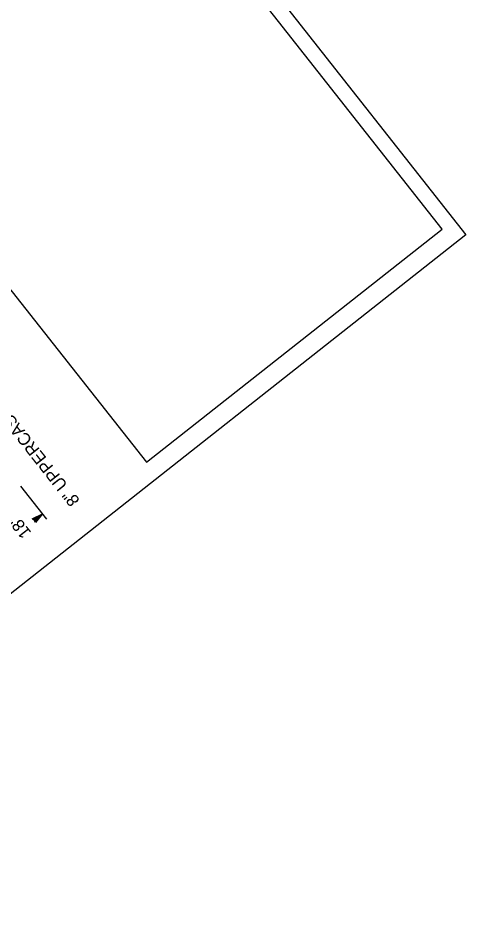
# Model space of a CAD drawing. Extents: x 672438 to 673980, y 1673259 to 1674850.
# Drawn here: x 673827.5 to 673979.7, y 1673259 to 1673565 of the extents above; entities that cross this region are included whole.
import ezdxf

# ---------------------------------------------------------------- set-up
doc = ezdxf.new("R2010")
doc.units = 0
doc.layers.add('61', color=7, linetype='Continuous')
doc.layers.add('Level 1', color=7, linetype='Continuous')

msp = doc.modelspace()

# ---------------------------------------------------------------- linework, layer by layer
at = {"layer": '61'}
msp.add_lwpolyline([(673971.58, 1673493.35), (673840.54, 1673659.58), (673740.04, 1673580.35), (673871.09, 1673414.13)], close=True, dxfattribs=at)
at = {"layer": 'Level 1'}
for p, q in [((673839.88, 1673668.73), (673979.67, 1673491.41)), ((673979.67, 1673491.41), (673684.88, 1673259.01)), ((673828.32, 1673406.06), (673837.15, 1673394.86)), ((673832.32, 1673394.9), (673835.78, 1673396.6)), ((673833.14, 1673394.4), (673832.47, 1673394.88)), ((673832.47, 1673394.88), (673832.69, 1673394.81)), ((673832.51, 1673394.95), (673835.36, 1673396.24)), ((673832.83, 1673394.76), (673832.51, 1673394.95)), ((673832.68, 1673394.91), (673835.52, 1673396.33)), ((673832.69, 1673394.81), (673832.68, 1673394.91)), ((673832.8, 1673394.84), (673835, 1673395.99)), ((673832.8, 1673394.84), (673834.92, 1673395.86)), ((673833.35, 1673394.27), (673832.8, 1673394.84)), ((673833.48, 1673394.14), (673832.8, 1673394.84)), ((673833.07, 1673394.45), (673832.83, 1673394.76)), ((673832.98, 1673394.78), (673834.49, 1673395.52)), ((673833.44, 1673394.27), (673832.98, 1673394.78)), ((673833.42, 1673394.69), (673833.06, 1673394.68)), ((673833.06, 1673394.68), (673833.44, 1673394.4)), ((673833.14, 1673394.74), (673834.1, 1673395.26)), ((673833.5, 1673394.42), (673833.14, 1673394.74)), ((673833.25, 1673394.69), (673833.77, 1673394.96)), ((673833.53, 1673394.54), (673833.25, 1673394.69)), ((673833.5, 1673394.62), (673833.42, 1673394.69)), ((673835, 1673395.99), (673833.44, 1673394.27)), ((673833.44, 1673394.4), (673833.94, 1673395.16)), ((673835.78, 1673396.6), (673833.46, 1673393.69)), ((673835.57, 1673396.36), (673833.48, 1673393.84)), ((673835.21, 1673396.09), (673833.48, 1673394.01)), ((673834.92, 1673395.86), (673833.48, 1673394.14)), ((673834.49, 1673395.52), (673833.5, 1673394.42)), ((673833.77, 1673394.96), (673833.5, 1673394.62)), ((673834.1, 1673395.26), (673833.53, 1673394.54)), ((673833.94, 1673395.16), (673834.2, 1673395.26)), ((673834.56, 1673395.61), (673834.12, 1673395.4)), ((673834.2, 1673395.26), (673834.56, 1673395.61)), ((673835.32, 1673396.3), (673834.52, 1673395.88)), ((673834.52, 1673395.88), (673835.21, 1673396.09)), ((673835.52, 1673396.33), (673835.32, 1673396.3)), ((673835.36, 1673396.24), (673835.57, 1673396.36)), ((673833.46, 1673393.69), (673833.07, 1673394.45)), ((673833.48, 1673393.84), (673833.14, 1673394.4)), ((673833.48, 1673394.01), (673833.35, 1673394.27))]:
    msp.add_line(p, q, dxfattribs=at)

# ---------------------------------------------------------------- texts
for s, p in [('8" UPPERCASE', (673848.67, 1673401.23)), ('18"', (673832.19, 1673390.29))]:
    msp.add_text(s, height=4.2, rotation=128.2505, dxfattribs=at).set_placement(p)

doc.saveas('drawing.dxf')
